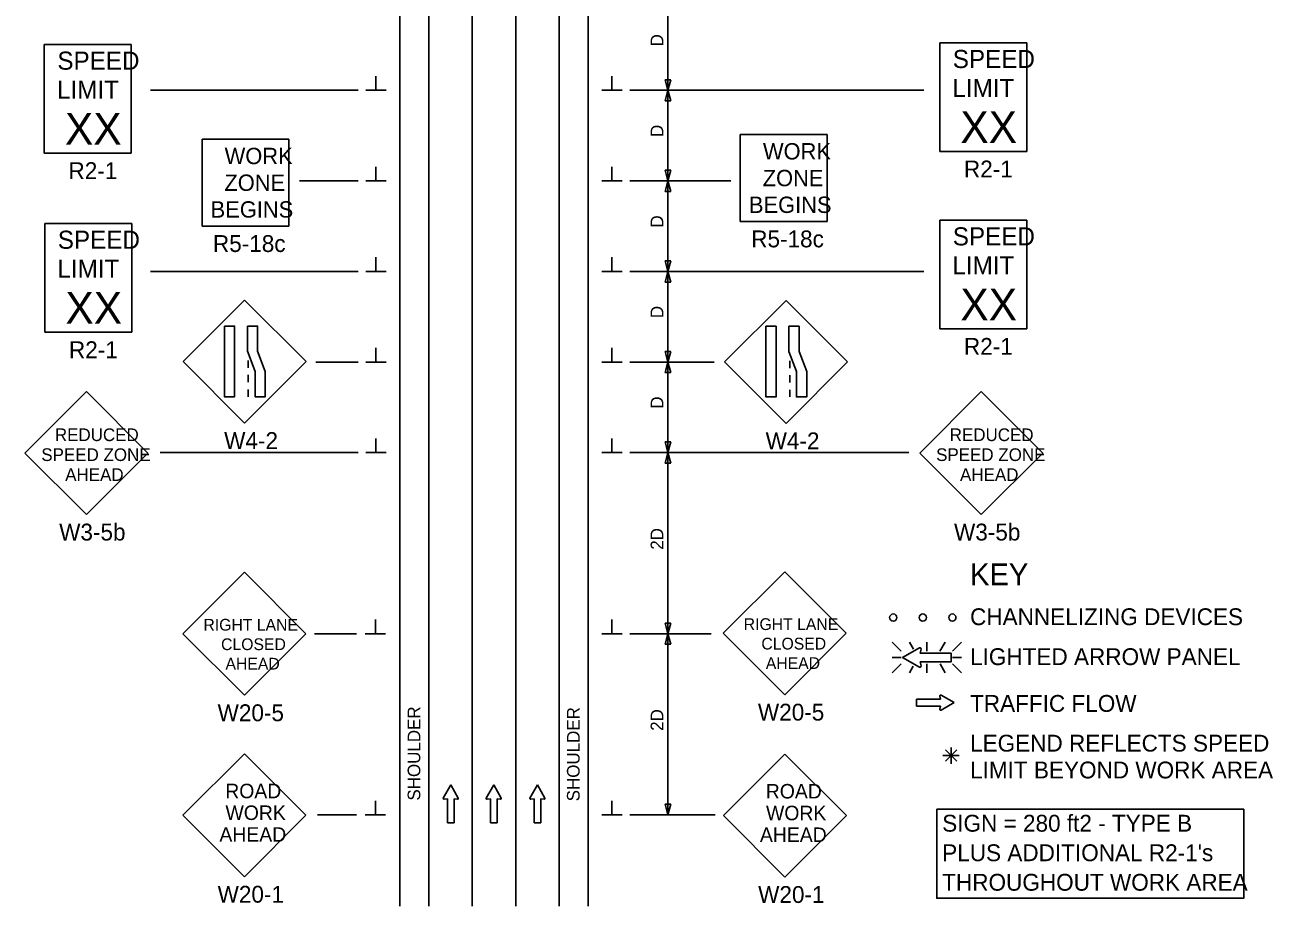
# Model space of a CAD drawing. Extents: x 16734 to 18479, y 5690 to 6927.
# Drawn here: x 16744 to 17433, y 6108 to 6594 of the extents above; entities that cross this region are included whole.
import ezdxf

# ---------------------------------------------------------------- set-up
doc = ezdxf.new("R2010")
doc.units = 0
for name, color, linetype in [('ALI_LEGAL_EX', 7, 'Continuous'), ('MT_SCRATCH_LEVEL_E', 7, 'Continuous'), ('PAVT_EDGE_EX', 7, 'Continuous'), ('TRAFFIC_SIGNS_PR', 7, 'Continuous'), ('TYPICAL_TEXT_DIMEN_EX', 7, 'Continuous'), ('TYPICAL_TEXT_DIMEN_PR', 7, 'Continuous')]:
    doc.layers.add(name, color=color, linetype=linetype)

msp = doc.modelspace()

# ---------------------------------------------------------------- linework, layer by layer
at = {"layer": 'ALI_LEGAL_EX'}
for p, q in [((16991.15, 6924.81), (16991.15, 6107.83)), ((17015.15, 6924.81), (17015.15, 6107.83))]:
    msp.add_line(p, q, dxfattribs=at)
for points in [[(16991.15, 6524.81), (16991.15, 6499.81)], [(17015.15, 6524.81), (17015.15, 6499.81)], [(16991.15, 6474.81), (16991.15, 6449.81)], [(17015.15, 6474.81), (17015.15, 6449.81)], [(16991.15, 6424.81), (16991.15, 6399.81)], [(17015.15, 6424.81), (17015.15, 6399.81)], [(16991.15, 6324.81), (16991.15, 6299.81)], [(17015.15, 6324.81), (17015.15, 6299.81)], [(16991.15, 6224.81), (16991.15, 6199.81)], [(17015.15, 6224.81), (17015.15, 6199.81)], [(16991.15, 6124.81), (16991.15, 6107.83)], [(17015.15, 6124.81), (17015.15, 6107.83)]]:
    msp.add_lwpolyline(points, dxfattribs=at)
at = {"layer": 'MT_SCRATCH_LEVEL_E'}
for p, q in [((17249.52, 6222.01), (17236.26, 6222.01)), ((17236.26, 6222.01), (17236.26, 6218.27)), ((17249.21, 6223.79), (17249.52, 6222.01)), ((17257.13, 6220.16), (17249.89, 6224.27)), ((17249.89, 6216.01), (17257.13, 6220.16)), ((17236.26, 6218.27), (17249.52, 6218.27)), ((17249.52, 6218.27), (17249.21, 6216.49)), ((16979.3, 6174.71), (16975.19, 6167.47)), ((16983.44, 6167.47), (16979.3, 6174.71)), ((17003, 6174.71), (16998.89, 6167.47)), ((17007.15, 6167.47), (17003, 6174.71)), ((17027.11, 6174.71), (17023, 6167.47)), ((17031.26, 6167.47), (17027.11, 6174.71)), ((16975.67, 6166.78), (16977.45, 6167.1)), ((16977.45, 6167.1), (16977.45, 6153.84)), ((16981.19, 6153.84), (16981.19, 6167.1)), ((16981.19, 6167.1), (16982.97, 6166.78)), ((16999.37, 6166.78), (17001.15, 6167.1)), ((17001.15, 6167.1), (17001.15, 6153.84)), ((17004.89, 6153.84), (17004.89, 6167.1)), ((17004.89, 6167.1), (17006.67, 6166.78)), ((17023.48, 6166.78), (17025.26, 6167.1)), ((17025.26, 6167.1), (17025.26, 6153.84)), ((17029, 6153.84), (17029, 6167.1)), ((17029, 6167.1), (17030.78, 6166.78)), ((16977.45, 6153.84), (16981.19, 6153.84)), ((17001.15, 6153.84), (17004.89, 6153.84)), ((17025.26, 6153.84), (17029, 6153.84))]:
    msp.add_line(p, q, dxfattribs=at)
for centre, start, end in [((17249.66, 6223.86), 60.42484, 189.96381), ((17249.66, 6216.42), 170.03619, 299.77312), ((16975.59, 6167.24), 150.42484, 279.96381), ((16983.04, 6167.25), 260.03619, 29.77312), ((16999.3, 6167.24), 150.42484, 279.96381), ((17006.74, 6167.25), 260.03619, 29.77312), ((17023.41, 6167.24), 150.42484, 279.96381), ((17030.85, 6167.25), 260.03619, 29.77312)]:
    msp.add_arc(centre, 0.463, start, end, dxfattribs=at)
at = {"layer": 'PAVT_EDGE_EX'}
for p, q in [((16951.15, 6927.15), (16951.15, 6107.83)), ((16967.15, 6927.15), (16967.15, 6107.83)), ((17039.15, 6927.15), (17039.15, 6107.83)), ((17055.15, 6927.15), (17055.15, 6107.83))]:
    msp.add_line(p, q, dxfattribs=at)
at = {"layer": 'TRAFFIC_SIGNS_PR'}
for p, q in [((16755, 6583.48), (16803, 6583.48)), ((16755, 6523.48), (16755, 6583.48)), ((16803, 6523.48), (16803, 6583.48)), ((17249.14, 6584.39), (17297.14, 6584.39)), ((17249.14, 6524.39), (17249.14, 6584.39)), ((17297.14, 6524.39), (17297.14, 6584.39)), ((16842.03, 6483.21), (16842.03, 6531.21)), ((16842.03, 6531.21), (16890.03, 6531.21)), ((16890.03, 6483.21), (16890.03, 6531.21)), ((17139.1, 6485.79), (17139.1, 6533.79)), ((17139.1, 6533.79), (17187.1, 6533.79)), ((17187.1, 6485.79), (17187.1, 6533.79)), ((16755, 6523.48), (16803, 6523.48)), ((17249.14, 6524.39), (17297.14, 6524.39)), ((16755.24, 6484.6), (16803.24, 6484.6)), ((16755.24, 6424.6), (16755.24, 6484.6)), ((16803.24, 6424.6), (16803.24, 6484.6)), ((16842.03, 6483.21), (16890.03, 6483.21)), ((17139.1, 6485.79), (17187.1, 6485.79)), ((17249.14, 6486.46), (17297.14, 6486.46)), ((17249.14, 6426.46), (17249.14, 6486.46)), ((17297.14, 6426.46), (17297.14, 6486.46)), ((16865.54, 6442.33), (16831.6, 6408.39)), ((16899.48, 6408.39), (16865.54, 6442.33)), ((17164.36, 6442.2), (17130.42, 6408.26)), ((17198.3, 6408.26), (17164.36, 6442.2)), ((17249.14, 6426.46), (17297.14, 6426.46)), ((16755.24, 6424.6), (16803.24, 6424.6)), ((16831.6, 6408.39), (16865.54, 6374.45)), ((16865.54, 6374.45), (16899.48, 6408.39)), ((16867.59, 6409.01), (16867.59, 6405.01)), ((17130.42, 6408.26), (17164.36, 6374.31)), ((17164.36, 6374.31), (17198.3, 6408.26)), ((17166.41, 6408.87), (17166.41, 6404.87)), ((16867.59, 6401.01), (16867.59, 6397.01)), ((17166.41, 6400.87), (17166.41, 6396.87)), ((16778.26, 6391.83), (16744.32, 6357.89)), ((16812.2, 6357.89), (16778.26, 6391.83)), ((16867.59, 6393.01), (16867.59, 6389.01)), ((17166.41, 6392.87), (17166.41, 6388.87)), ((17272.08, 6391.83), (17238.14, 6357.89)), ((17306.02, 6357.89), (17272.08, 6391.83)), ((16744.32, 6357.89), (16778.26, 6323.94)), ((16778.26, 6323.94), (16812.2, 6357.89)), ((17238.14, 6357.89), (17272.08, 6323.94)), ((17272.08, 6323.94), (17306.02, 6357.89)), ((16865.41, 6292.07), (16831.47, 6258.13)), ((16899.35, 6258.13), (16865.41, 6292.07)), ((17163.58, 6292.4), (17129.64, 6258.46)), ((17197.52, 6258.46), (17163.58, 6292.4)), ((16831.47, 6258.13), (16865.41, 6224.19)), ((16865.41, 6224.19), (16899.35, 6258.13)), ((17129.64, 6258.46), (17163.58, 6224.52)), ((17163.58, 6224.52), (17197.52, 6258.46)), ((17222.94, 6253.54), (17227.87, 6248.61)), ((17234.7, 6249.72), (17232.5, 6253.55)), ((17242.02, 6248.61), (17242.02, 6253.55)), ((17249.26, 6248.61), (17252.11, 6253.55)), ((17256.17, 6248.61), (17261.11, 6253.55)), ((17227.87, 6245.06), (17222.94, 6245.06)), ((17222.94, 6236.57), (17227.87, 6241.5)), ((17232.45, 6236.57), (17234.56, 6240.23)), ((17242.02, 6241.5), (17242.02, 6236.57)), ((17252.15, 6236.57), (17249.3, 6241.5)), ((17256.17, 6245.06), (17261.11, 6245.06)), ((17256.17, 6241.5), (17261.11, 6236.56)), ((16865.43, 6191.87), (16831.49, 6157.93)), ((16899.37, 6157.93), (16865.43, 6191.87)), ((17163.72, 6191.73), (17129.78, 6157.79)), ((17197.66, 6157.79), (17163.72, 6191.73)), ((16831.49, 6157.93), (16865.43, 6123.99)), ((16865.43, 6123.99), (16899.37, 6157.93)), ((17129.78, 6157.79), (17163.72, 6123.85)), ((17163.72, 6123.85), (17197.66, 6157.79))]:
    msp.add_line(p, q, dxfattribs=at)
for points in [[(16854.42, 6428.06), (16854.42, 6389.01), (16860.04, 6389.01), (16860.04, 6428.06)], [(16867.09, 6428.06), (16867.09, 6414.09), (16871.27, 6402.98), (16871.27, 6389.01), (16876.89, 6389.01), (16876.89, 6402.98), (16872.71, 6414.09), (16872.71, 6428.06)], [(17153.24, 6427.93), (17153.24, 6388.87), (17158.86, 6388.87), (17158.86, 6427.93)], [(17165.91, 6427.93), (17165.91, 6413.95), (17170.09, 6402.85), (17170.09, 6388.87), (17175.71, 6388.87), (17175.71, 6402.85), (17171.53, 6413.95), (17171.53, 6427.93)]]:
    msp.add_lwpolyline(points, close=True, dxfattribs=at)
for points in [[(17237.95, 6250.33), (17228.66, 6245.06), (17237.95, 6239.73)], [(17238.83, 6240.36), (17238.42, 6242.63), (17255.44, 6242.63), (17255.44, 6247.43), (17238.42, 6247.43), (17238.83, 6249.71)]]:
    msp.add_lwpolyline(points, dxfattribs=at)
for centre in [(17223.5, 6267.09), (17239.8, 6267.09), (17256.1, 6267.09)]:
    msp.add_circle(centre, 2, dxfattribs=at)
for centre, radius, start, end in [((17238.24, 6249.81), 0.598, 350.73078, 118.89165), ((17238.24, 6240.26), 0.597, 241.48329, 9.95933)]:
    msp.add_arc(centre, radius, start, end, dxfattribs=at)
at = {"layer": 'TYPICAL_TEXT_DIMEN_EX'}
msp.add_lwpolyline([(17247.5, 6161.3), (17416.95, 6161.3), (17416.95, 6112.11), (17247.5, 6112.11)], close=True, dxfattribs=at)
at = {"layer": 'TYPICAL_TEXT_DIMEN_PR'}
for p, q in [((17099.15, 6608.18), (17099.15, 6558.18)), ((16938.03, 6558.18), (16938.03, 6565.97)), ((17068.28, 6558.18), (17068.28, 6565.97)), ((17099.15, 6558.18), (17097.58, 6564.04)), ((17097.58, 6564.04), (17099.15, 6564.04)), ((17099.15, 6564.04), (17100.72, 6564.04)), ((17100.72, 6564.04), (17099.15, 6558.18)), ((16813.56, 6558.18), (16928.15, 6558.18)), ((16932.4, 6558.18), (16943.65, 6558.18)), ((17073.9, 6558.18), (17062.65, 6558.18)), ((17240.31, 6558.18), (17078.15, 6558.18)), ((17097.58, 6552.32), (17099.15, 6558.18)), ((17099.15, 6558.18), (17099.15, 6508.18)), ((17099.15, 6558.18), (17100.72, 6552.32)), ((17099.15, 6552.32), (17097.58, 6552.32)), ((17100.72, 6552.32), (17099.15, 6552.32)), ((16938.03, 6508.18), (16938.03, 6515.97)), ((17068.28, 6508.18), (17068.28, 6515.97)), ((17099.15, 6508.18), (17097.58, 6514.04)), ((17097.58, 6514.04), (17099.15, 6514.04)), ((17099.15, 6514.04), (17100.72, 6514.04)), ((17100.72, 6514.04), (17099.15, 6508.18)), ((16895.85, 6508.18), (16928.15, 6508.18)), ((16932.4, 6508.18), (16943.65, 6508.18)), ((17073.9, 6508.18), (17062.65, 6508.18)), ((17133.78, 6508.18), (17078.15, 6508.18)), ((17097.58, 6502.32), (17099.15, 6508.18)), ((17099.15, 6502.32), (17097.58, 6502.32)), ((17099.15, 6508.18), (17099.15, 6458.18)), ((17099.15, 6508.18), (17100.72, 6502.32)), ((17100.72, 6502.32), (17099.15, 6502.32)), ((16938.03, 6458.18), (16938.03, 6465.97)), ((17068.28, 6458.18), (17068.28, 6465.97)), ((17099.15, 6458.18), (17097.58, 6464.04)), ((17097.58, 6464.04), (17099.15, 6464.04)), ((17099.15, 6464.04), (17100.72, 6464.04)), ((17100.72, 6464.04), (17099.15, 6458.18)), ((16813.56, 6458.18), (16928.15, 6458.18)), ((16932.4, 6458.18), (16943.65, 6458.18)), ((17073.9, 6458.18), (17062.65, 6458.18)), ((17240.31, 6458.18), (17078.15, 6458.18)), ((17097.58, 6452.32), (17099.15, 6458.18)), ((17099.15, 6458.18), (17099.15, 6408.18)), ((17099.15, 6458.18), (17100.72, 6452.32)), ((17099.15, 6452.32), (17097.58, 6452.32)), ((17100.72, 6452.32), (17099.15, 6452.32)), ((16938.03, 6408.18), (16938.03, 6415.97)), ((17068.28, 6408.18), (17068.28, 6415.97)), ((17099.15, 6408.18), (17097.58, 6414.04)), ((17097.58, 6414.04), (17099.15, 6414.04)), ((17099.15, 6414.04), (17100.72, 6414.04)), ((17100.72, 6414.04), (17099.15, 6408.18)), ((16904.88, 6408.18), (16928.15, 6408.18)), ((16932.4, 6408.18), (16943.65, 6408.18)), ((17073.9, 6408.18), (17062.65, 6408.18)), ((17124.73, 6408.18), (17078.15, 6408.18)), ((17097.58, 6402.32), (17099.15, 6408.18)), ((17099.15, 6408.18), (17099.15, 6358.18)), ((17099.15, 6408.18), (17100.72, 6402.32)), ((17099.15, 6402.32), (17097.58, 6402.32)), ((17100.72, 6402.32), (17099.15, 6402.32)), ((16938.03, 6358.18), (16938.03, 6365.97)), ((17068.28, 6358.18), (17068.28, 6365.97)), ((16818.93, 6358.18), (16928.15, 6358.18)), ((16932.4, 6358.18), (16943.65, 6358.18)), ((17073.9, 6358.18), (17062.65, 6358.18)), ((17232.17, 6358.18), (17078.15, 6358.18)), ((17099.15, 6358.18), (17097.58, 6364.04)), ((17097.58, 6364.04), (17099.15, 6364.04)), ((17097.58, 6352.32), (17099.15, 6358.18)), ((17099.15, 6364.04), (17100.72, 6364.04)), ((17100.72, 6364.04), (17099.15, 6358.18)), ((17099.15, 6358.18), (17099.15, 6258.18)), ((17099.15, 6358.18), (17100.72, 6352.32)), ((17099.15, 6352.32), (17097.58, 6352.32)), ((17100.72, 6352.32), (17099.15, 6352.32)), ((16937.74, 6258.18), (16937.74, 6265.97)), ((17068.28, 6258.18), (17068.28, 6265.97)), ((17099.15, 6258.18), (17097.58, 6264.04)), ((17097.58, 6264.04), (17099.15, 6264.04)), ((17099.15, 6264.04), (17100.72, 6264.04)), ((17100.72, 6264.04), (17099.15, 6258.18)), ((16927.29, 6258.18), (16904.06, 6258.18)), ((16943.36, 6258.18), (16932.11, 6258.18)), ((17073.9, 6258.18), (17062.65, 6258.18)), ((17123.07, 6258.18), (17078.15, 6258.18)), ((17097.58, 6252.32), (17099.15, 6258.18)), ((17099.15, 6258.18), (17099.15, 6158.18)), ((17099.15, 6258.18), (17100.72, 6252.32)), ((17099.15, 6252.32), (17097.58, 6252.32)), ((17100.72, 6252.32), (17099.15, 6252.32)), ((17252.28, 6194.1), (17258.65, 6187.73)), ((17258.65, 6194.1), (17252.28, 6187.73)), ((17255.46, 6190.91), (17255.46, 6195.37)), ((17255.46, 6190.91), (17250.93, 6190.91)), ((17255.46, 6190.91), (17258.65, 6190.91)), ((17255.46, 6190.91), (17259.94, 6190.91)), ((17255.46, 6190.91), (17255.46, 6186.41)), ((16937.74, 6158.18), (16937.74, 6165.97)), ((17068.28, 6158.18), (17068.28, 6165.97)), ((16927.29, 6158.18), (16905.71, 6158.18)), ((16943.36, 6158.18), (16932.11, 6158.18)), ((17073.9, 6158.18), (17062.65, 6158.18)), ((17125.14, 6158.18), (17078.15, 6158.18)), ((17099.15, 6158.18), (17097.58, 6164.04)), ((17097.58, 6164.04), (17099.15, 6164.04)), ((17099.15, 6164.04), (17100.72, 6164.04)), ((17100.72, 6164.04), (17099.15, 6158.18))]:
    msp.add_line(p, q, dxfattribs=at)

# ---------------------------------------------------------------- texts
at = {"layer": 'TRAFFIC_SIGNS_PR'}
for s, height, p in [('SPEED', 10, (16762.2, 6569.56)), ('SPEED', 10, (17256.35, 6570.47)), ('LIMIT', 10, (17256.15, 6554.47)), ('LIMIT', 10, (16762, 6553.56)), ('XX', 17.538, (16766.39, 6528.18)), ('XX', 17.538, (17260.53, 6529.09)), ('WORK', 9.021, (16854.53, 6517.42)), ('WORK', 9.021, (17151.59, 6520)), ('R2-1', 9.3, (16768.34, 6509.18)), ('R2-1', 9.3, (17262.49, 6510.09)), ('ZONE', 9.021, (16854.38, 6502.66)), ('ZONE', 9.021, (17151.45, 6505.24)), ('BEGINS', 9.021, (16846.79, 6487.9)), ('BEGINS', 9.021, (17143.86, 6490.47)), ('SPEED', 10, (17256.35, 6472.54)), ('SPEED', 10, (16762.45, 6470.68)), ('R5-18c', 9.3, (16848.05, 6468.92)), ('R5-18c', 9.3, (17145.11, 6471.49)), ('LIMIT', 10, (16762.25, 6454.68)), ('LIMIT', 10, (17256.15, 6456.54)), ('XX', 17.538, (16766.63, 6429.3)), ('XX', 17.538, (17260.53, 6431.16)), ('R2-1', 9.3, (16768.59, 6410.3)), ('R2-1', 9.3, (17262.49, 6412.16)), ('REDUCED', 7, (16760.83, 6364.52)), ('REDUCED', 7, (17254.65, 6364.52)), ('W4-2', 9.3, (16854.24, 6360.15)), ('W4-2', 9.3, (17153.06, 6360.01)), ('SPEED ZONE', 7, (16753.33, 6353.52)), ('SPEED ZONE', 7, (17247.14, 6353.52)), ('AHEAD', 7, (16766.53, 6342.52)), ('AHEAD', 7, (17260.34, 6342.52)), ('W3-5b', 9.3, (16763.2, 6309.64)), ('W3-5b', 9.3, (17257.02, 6309.64)), ('RIGHT LANE', 6.5, (16842.81, 6259.87)), ('RIGHT LANE', 6.5, (17140.98, 6260.21)), ('CLOSED', 6.5, (16852.55, 6249.12)), ('CLOSED', 6.5, (17150.72, 6249.46)), ('AHEAD', 6.5, (16854.98, 6238.37)), ('AHEAD', 6.5, (17153.16, 6238.71)), ('W20-5', 9.3, (17148.8, 6210.22)), ('W20-5', 9.3, (16850.63, 6209.89)), ('ROAD', 8, (16854.85, 6167.35)), ('ROAD', 8, (17153.15, 6167.21)), ('WORK', 8, (16854.99, 6155.35)), ('WORK', 8, (17153.28, 6155.21)), ('AHEAD', 8, (16851.63, 6143.35)), ('AHEAD', 8, (17149.92, 6143.21)), ('W20-1', 9.3, (16850.64, 6109.69)), ('W20-1', 9.3, (17148.93, 6109.55))]:
    msp.add_text(s, height=height, dxfattribs=at).set_placement(p)
at = {"layer": 'TYPICAL_TEXT_DIMEN_EX'}
for s, height, p in [('KEY', 12, (17265.88, 6284.95)), ('CHANNELIZING DEVICES', 9.3, (17265.88, 6262.9)), ('LIGHTED ARROW PANEL', 9.3, (17265.88, 6240.85)), ('TRAFFIC FLOW', 9.3, (17265.88, 6215.05)), ('LEGEND REFLECTS SPEED', 9.3, (17265.88, 6193.1)), ('LIMIT BEYOND WORK AREA', 9.3, (17265.88, 6178.3)), ('SIGN = 280 ft2 - TYPE B', 9.3, (17250.51, 6148.9)), ("PLUS ADDITIONAL R2-1's", 9.3, (17250.51, 6132.6)), ('THROUGHOUT WORK AREA', 9.3, (17250.51, 6116.3))]:
    msp.add_text(s, height=height, dxfattribs=at).set_placement(p)
at = {"layer": 'TYPICAL_TEXT_DIMEN_PR'}
for s, p in [('D', (17096.59, 6582.4)), ('D', (17096.59, 6532.4)), ('D', (17096.59, 6482.4)), ('D', (17096.59, 6432.4)), ('D', (17096.59, 6382.4)), ('2D', (17096.59, 6304.55)), ('SHOULDER', (16962.51, 6166.05)), ('SHOULDER', (17050.43, 6165.64)), ('2D', (17096.59, 6204.55))]:
    msp.add_text(s, height=7, rotation=90, dxfattribs=at).set_placement(p)

doc.saveas('drawing.dxf')
